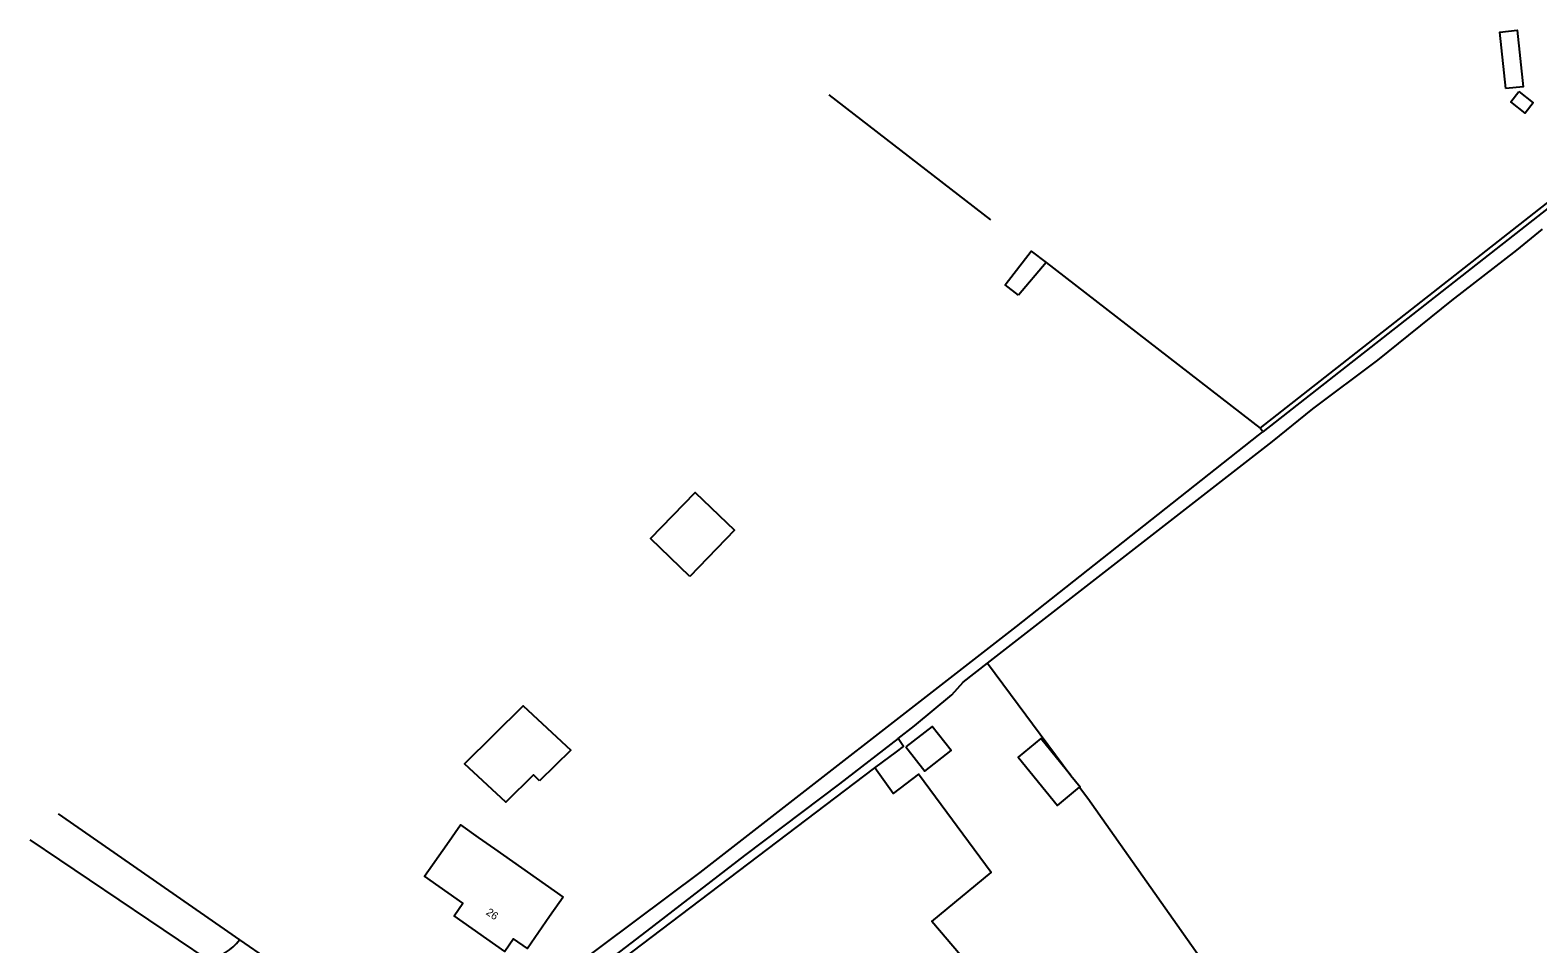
# Model space of a CAD drawing. Extents: x 163863 to 164644, y 379566 to 382155.
# Drawn here: x 164143.6 to 164337.9, y 381886.6 to 382004.3 of the extents above; entities that cross this region are included whole.
import ezdxf

# ---------------------------------------------------------------- set-up
doc = ezdxf.new("R2010")
doc.units = 0
for name, color, linetype in [('IMGEO_Grasland_agrarisch', 7, 'Continuous'), ('IMGEO_Grasland_overig', 7, 'Continuous'), ('IMGEO_Groenvoorziening', 7, 'Continuous'), ('IMGEO_Hek', 7, 'Continuous'), ('IMGEO_Pand', 7, 'Continuous'), ('IMGEO_Pand_nummerreeks', 7, 'Continuous'), ('IMGEO_Rijbaan_lokaal_gesloten', 7, 'Continuous'), ('IMGEO_Voetpad_open', 7, 'Continuous'), ('IMGEO_Waterloop', 7, 'Continuous')]:
    doc.layers.add(name, color=color, linetype=linetype)

msp = doc.modelspace()

# ---------------------------------------------------------------- linework, layer by layer
at = {"layer": 'IMGEO_Grasland_agrarisch'}
for points in [[(164266.94, 381922.74), (164277.67, 381908.3)], [(164278.81, 381906.76), (164279.85, 381905.36), (164303.69, 381871.55), (164284.62, 381860.24), (164259.76, 381889.45), (164267.39, 381895.77), (164258.03, 381908.47), (164254.79, 381905.94), (164252.4, 381909.27)]]:
    msp.add_lwpolyline(points, dxfattribs=at)
at = {"layer": 'IMGEO_Grasland_overig'}
for points in [[(164302.43, 381952.58), (164302.08, 381953.03), (164345.16, 381986.83), (164370.62, 381969.69)], [(164252.4, 381909.27), (164253.39, 381910), (164255.22, 381911.35), (164256.12, 381912.02), (164255.41, 381913.05)], [(164335.01, 381775.05), (164322.43, 381783.41), (164286.01, 381809.75), (164256.46, 381829.63), (164222.91, 381852.77), (164211.76, 381860.7), (164201.66, 381868.74), (164208.65, 381876.06), (164252.4, 381909.27)]]:
    msp.add_lwpolyline(points, dxfattribs=at)
at = {"layer": 'IMGEO_Groenvoorziening'}
msp.add_lwpolyline([(164147.19, 381903.34), (164170.55, 381887.1)], dxfattribs=at)
at = {"layer": 'IMGEO_Hek'}
for points in [[(164267.38, 381979.87), (164246.54, 381995.99)], [(164302.08, 381953.03), (164345.16, 381986.83), (164370.62, 381969.69)], [(164274.49, 381974.37), (164302.08, 381953.03)], [(164147.19, 381903.34), (164170.55, 381887.1)]]:
    msp.add_lwpolyline(points, dxfattribs=at)
at = {"layer": 'IMGEO_Pand'}
for points in [[(164333.74, 381996.79), (164332.94, 382004.08), (164335.17, 382004.33), (164335.97, 381997.03), (164333.74, 381996.79)], [(164335.42, 381996.4), (164337.24, 381994.94), (164336.2, 381993.64), (164334.38, 381995.1), (164335.42, 381996.4)], [(164270.95, 381970.17), (164269.22, 381971.51), (164272.58, 381975.85), (164274.49, 381974.37), (164270.95, 381970.17)], [(164228.58, 381933.92), (164223.53, 381938.8), (164229.28, 381944.76), (164234.33, 381939.88), (164228.58, 381933.92)], [(164209.23, 381907.58), (164208.45, 381908.38), (164204.86, 381904.85), (164199.55, 381909.79), (164207.12, 381917.25), (164213.27, 381911.55), (164209.23, 381907.58)], [(164256.43, 381911.96), (164258.87, 381908.85), (164262.24, 381911.49), (164259.8, 381914.6), (164256.43, 381911.96)], [(164277.67, 381908.3), (164273.81, 381913.03), (164270.87, 381910.64), (164275.94, 381904.42), (164278.81, 381906.76)], [(164277.67, 381908.3), (164278.88, 381906.82), (164278.81, 381906.76)], [(164212.28, 381892.59), (164210.52, 381890.09), (164207.65, 381886), (164205.88, 381887.24), (164204.74, 381885.61), (164198.2, 381890.21), (164199.34, 381891.83), (164194.39, 381895.31), (164197.26, 381899.4), (164199.02, 381901.91), (164201.32, 381900.29), (164203.41, 381898.82), (164212.28, 381892.59)]]:
    msp.add_lwpolyline(points, dxfattribs=at)
at = {"layer": 'IMGEO_Rijbaan_lokaal_gesloten'}
msp.add_lwpolyline([(164166.5, 381884.54), (164143.58, 381899.97)], dxfattribs=at)
at = {"layer": 'IMGEO_Voetpad_open'}
msp.add_lwpolyline([(164170.55, 381887.1), (164176.8, 381882.79)], dxfattribs=at)
msp.add_arc((164165.05, 381891.33), 6.94, 282.0831, 322.465, dxfattribs=at)
at = {"layer": 'IMGEO_Waterloop'}
for points in [[(164370.71, 381967.54), (164346.03, 381985.72), (164345.16, 381985.92), (164344.76, 381985.77), (164302.43, 381952.58)], [(164266.94, 381922.74), (164303.65, 381951.33), (164308.86, 381955.55), (164317.22, 381961.8), (164326.77, 381969.48), (164335.15, 381975.96), (164338.46, 381978.67)], [(164195.39, 381868.58), (164197.25, 381870.26), (164204.74, 381876.96), (164229.91, 381895.79), (164270.69, 381927.48), (164301.86, 381952.13), (164302.43, 381952.58)], [(164255.41, 381913.05), (164257.52, 381914.69), (164262.34, 381918.68), (164263.8, 381920.29), (164266.94, 381922.74)], [(164255.41, 381913.05), (164247.86, 381907.22), (164235.64, 381897.96), (164222.99, 381888.23), (164210.56, 381878.7), (164203.18, 381872.99), (164199.68, 381869.41), (164198.75, 381868.31), (164200.24, 381867.21), (164203.61, 381864.73), (164212.77, 381858.25), (164219.74, 381853.04), (164219.77, 381853.02)]]:
    msp.add_lwpolyline(points, dxfattribs=at)

# ---------------------------------------------------------------- texts
at = {"layer": 'IMGEO_Pand_nummerreeks'}
msp.add_text('26', height=1, rotation=324.9121, dxfattribs=at).set_placement((164202.24, 381890.45))

doc.saveas('drawing.dxf')
